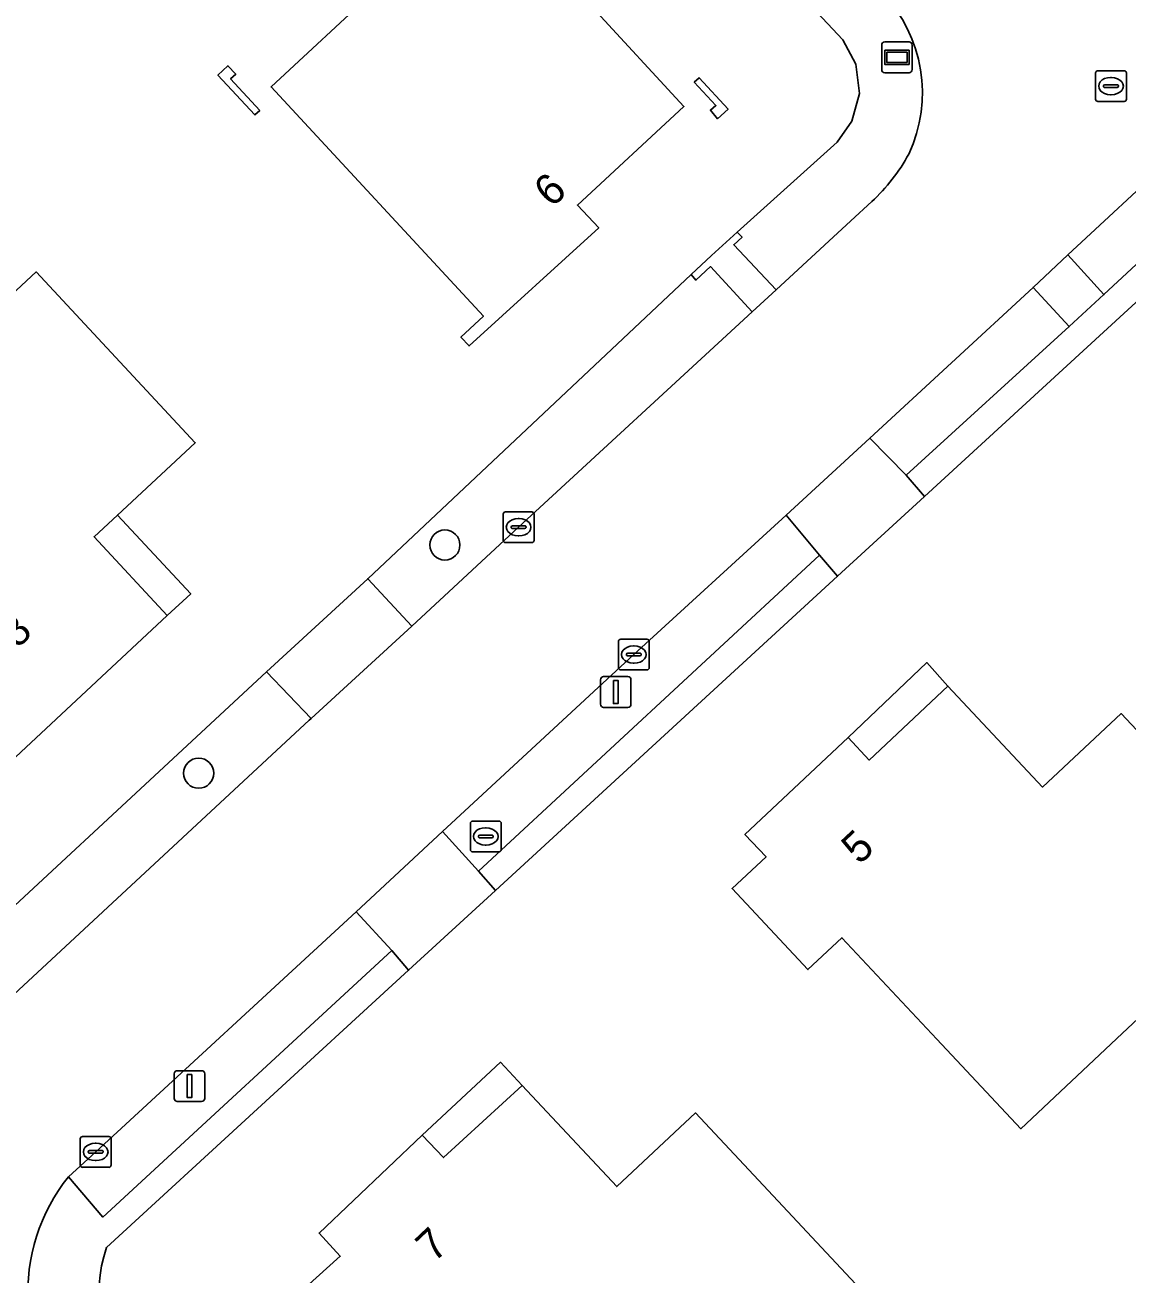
# Model space of a CAD drawing. Extents: x 162661 to 163484, y 380247 to 381230.
# Drawn here: x 163294.19 to 163329.99, y 380893.22 to 380933.79 of the extents above; entities that cross this region are included whole.
import ezdxf

# ---------------------------------------------------------------- set-up
doc = ezdxf.new("R2010")
doc.units = 0
for name, color, linetype in [('IMGEO_Berm_groen', 7, 'Continuous'), ('IMGEO_Boom', 7, 'Continuous'), ('IMGEO_Brandkraan', 7, 'Continuous'), ('IMGEO_Erf', 7, 'Continuous'), ('IMGEO_Groenvoorziening', 7, 'Continuous'), ('IMGEO_Haag', 7, 'Continuous'), ('IMGEO_Kolk', 7, 'Continuous'), ('IMGEO_Lichtmast', 7, 'Continuous'), ('IMGEO_Pand', 7, 'Continuous'), ('IMGEO_Pand_nummerreeks', 7, 'Continuous'), ('IMGEO_Pand_overbouw', 7, 'Continuous'), ('IMGEO_Parkeervlak_halfverhard', 7, 'Continuous'), ('IMGEO_Rijbaan_lokaal_gesloten', 7, 'Continuous'), ('IMGEO_Rioolput', 7, 'Continuous'), ('IMGEO_Straatnaambord', 7, 'Continuous'), ('IMGEO_Voetpad_open', 7, 'Continuous')]:
    doc.layers.add(name, color=color, linetype=linetype)

msp = doc.modelspace()

# ---------------------------------------------------------------- linework, layer by layer
at = {"layer": 'IMGEO_Berm_groen'}
for points in [[(163293.024, 380958.913), (163294.252, 380959.688), (163295.699, 380959.641), (163296.884, 380958.739), (163320.761, 380933.306), (163321.184, 380932.515), (163321.299, 380931.564), (163321.057, 380930.657), (163320.579, 380929.984), (163317.332, 380927.055), (163317.486, 380926.898), (163317.218, 380926.646), (163318.596, 380925.187), (163321.019, 380927.42), (163321.7, 380928.048)], [(163296.844, 380894.082), (163306.653, 380903.087), (163306.114, 380903.726), (163296.724, 380895.071), (163295.607, 380896.382)]]:
    msp.add_lwpolyline(points, dxfattribs=at)
for points in [[(163317.82, 380924.471), (163316.465, 380925.941), (163315.99, 380925.496), (163315.837, 380925.681), (163305.328, 380915.802), (163306.754, 380914.26), (163310.229, 380917.474)], [(163292.603, 380901.179), (163303.421, 380911.205), (163303.486, 380911.264), (163302.041, 380912.777), (163278.098, 380890.562), (163279.38, 380889.205), (163283.878, 380893.181), (163284.042, 380893.331)]]:
    msp.add_lwpolyline(points, close=True, dxfattribs=at)
for centre, radius, start, end in [((163318.634, 380931.58), 4.71, 335.074, 43.3446), ((163317.482, 380932.576), 6.188, 312.9676, 331.2004), ((163300.314, 380892.617), 6.028, 141.3438, 183.419), ((163300.705, 380892.693), 4.103, 160.2199, 228.0468)]:
    msp.add_arc(centre, radius, start, end, dxfattribs=at)
at = {"layer": 'IMGEO_Boom'}
for centre in [(163307.833, 380916.898), (163299.834, 380909.487)]:
    msp.add_circle(centre, 0.489, dxfattribs=at)
at = {"layer": 'IMGEO_Brandkraan'}
for p, q in [((163308.661, 380907.006), (163308.661, 380907.858)), ((163308.736, 380907.932), (163309.588, 380907.932)), ((163309.149, 380907.712), (163309.174, 380907.712)), ((163309.662, 380907.858), (163309.662, 380907.006)), ((163308.92, 380907.426), (163308.92, 380907.438)), ((163309.358, 380907.389), (163308.96, 380907.389)), ((163308.963, 380907.475), (163309.361, 380907.475)), ((163309.404, 380907.438), (163309.404, 380907.426)), ((163309.588, 380906.932), (163308.736, 380906.932)), ((163309.172, 380907.152), (163309.147, 380907.152))]:
    msp.add_line(p, q, dxfattribs=at)
for points in [[(163308.661, 380907.006), (163308.661, 380907.858)], [(163308.736, 380907.932), (163309.588, 380907.932)], [(163309.662, 380907.858), (163309.662, 380907.006)], [(163309.588, 380906.932), (163308.736, 380906.932)]]:
    msp.add_lwpolyline(points, dxfattribs=at)
for centre, radius, start, end in [((163308.738, 380907.856), 0.0765, 91.552, 178.448), ((163308.738, 380907.856), 0.0765, 91.552, 178.448), ((163309.586, 380907.856), 0.0765, 1.552, 88.448), ((163309.586, 380907.856), 0.0765, 1.552, 88.448), ((163308.96, 380907.435), 0.0403, 85.8775, 175.7526), ((163308.957, 380907.425), 0.0366, 178.938, 274.7102), ((163309.361, 380907.432), 0.043, 264.8664, 352.4533), ((163309.365, 380907.437), 0.0386, 1.7309, 96.639), ((163308.738, 380907.008), 0.0765, 181.552, 268.448), ((163308.738, 380907.008), 0.0765, 181.552, 268.448), ((163309.586, 380907.008), 0.0765, 271.552, 358.448), ((163309.586, 380907.008), 0.0765, 271.552, 358.448)]:
    msp.add_arc(centre, radius, start, end, dxfattribs=at)
for centre, major_axis, ratio, start_param, end_param in [((163309.148, 380907.432), (-0.387, 0.002), 0.722429, 4.712389, 7.853982), ((163309.173, 380907.432), (-0.39, 0.002), 0.717154, 1.570796, 4.712389)]:
    msp.add_ellipse(centre, major_axis=major_axis, ratio=ratio, start_param=start_param, end_param=end_param, dxfattribs=at)
at = {"layer": 'IMGEO_Erf'}
for points in [[(163404.993, 380933.536), (163403.462, 380935.161), (163390.657, 380948.856), (163386.451, 380953.455), (163376.71, 380963.784), (163373.198, 380964.214), (163372.923, 380964.017), (163339.792, 380933.51), (163323.416, 380918.477), (163320.591, 380915.883), (163309.478, 380905.68), (163306.653, 380903.087), (163296.844, 380894.082)], [(163278.098, 380890.562), (163302.041, 380912.777), (163305.328, 380915.802), (163315.837, 380925.681), (163316.494, 380926.299), (163317.332, 380927.055), (163320.579, 380929.984), (163321.057, 380930.657), (163321.299, 380931.564), (163321.184, 380932.515), (163320.761, 380933.306), (163296.884, 380958.739), (163295.699, 380959.641), (163294.252, 380959.688), (163293.024, 380958.913), (163283.361, 380949.868), (163280.252, 380946.958), (163279.693, 380946.435), (163279.155, 380946.024), (163267.646, 380936.418), (163264.752, 380934.006)]]:
    msp.add_lwpolyline(points, dxfattribs=at)
for points in [[(163302.185, 380931.776), (163305.624, 380934.965), (163304.635, 380936.032), (163308.825, 380939.918), (163309.065, 380939.658), (163308.326, 380938.983), (163309.719, 380937.481), (163310.453, 380938.16), (163313.364, 380935.016), (163312.639, 380934.34), (163315.599, 380931.142), (163312.137, 380927.939), (163312.833, 380927.195), (163308.617, 380923.363), (163308.352, 380923.649), (163309.083, 380924.327)], [(163300.46, 380932.16), (163300.786, 380932.463), (163301.041, 380932.188), (163300.872, 380932.032), (163301.821, 380931.009), (163301.663, 380930.863)], [(163315.932, 380931.927), (163316.09, 380932.073), (163317.034, 380931.053), (163316.692, 380930.741), (163316.459, 380931.022), (163316.635, 380931.168)], [(163289.384, 380920.952), (163294.56, 380925.767), (163299.721, 380920.22), (163297.196, 380917.871), (163296.437, 380917.165), (163298.814, 380914.61), (163292.897, 380909.095), (163292.215, 380909.827), (163291.121, 380908.79), (163288.672, 380911.424), (163289.774, 380912.45), (163287.391, 380915.013), (163291.421, 380918.761)], [(163329.836, 380901.028), (163326.546, 380897.941), (163323.815, 380900.853), (163320.728, 380904.144), (163319.628, 380903.111), (163317.164, 380905.738), (163318.266, 380906.772), (163317.581, 380907.499), (163320.931, 380910.641), (163321.617, 380909.914), (163324.172, 380912.316), (163327.25, 380909.035), (163329.806, 380911.425), (163335.008, 380905.88)], [(163313.418, 380896.062), (163315.974, 380898.453), (163321.176, 380892.908), (163316.004, 380888.056), (163313.273, 380890.967), (163310.003, 380887.9), (163306.825, 380891.161), (163305.766, 380890.171), (163303.313, 380892.798), (163304.434, 380893.8), (163303.747, 380894.55), (163307.099, 380897.73), (163307.787, 380897.005), (163310.338, 380899.346)]]:
    msp.add_lwpolyline(points, close=True, dxfattribs=at)
msp.add_arc((163300.705, 380892.693), 4.103, 160.2199, 228.0468, dxfattribs=at)
at = {"layer": 'IMGEO_Groenvoorziening'}
msp.add_lwpolyline([(163378.593, 380962.733), (163378.306, 380963.06), (163378.763, 380963.459), (163374.975, 380967.47), (163374.087, 380966.646), (163329.24, 380925.031), (163328.116, 380923.988), (163322.814, 380919.162), (163323.416, 380918.477), (163339.792, 380933.51), (163372.923, 380964.017), (163373.198, 380964.214), (163376.71, 380963.784), (163386.451, 380953.455), (163390.657, 380948.856), (163403.462, 380935.161), (163404.993, 380933.536)], dxfattribs=at)
msp.add_lwpolyline([(163320.591, 380915.883), (163320.001, 380916.57), (163308.921, 380906.309), (163309.478, 380905.68)], close=True, dxfattribs=at)
at = {"layer": 'IMGEO_Haag'}
msp.add_lwpolyline([(163320.591, 380915.883), (163320.001, 380916.57), (163308.921, 380906.309), (163309.478, 380905.68)], close=True, dxfattribs=at)
at = {"layer": 'IMGEO_Kolk'}
for p, q in [((163309.728, 380917.048), (163309.728, 380917.9)), ((163309.803, 380917.974), (163310.655, 380917.974)), ((163310.729, 380917.9), (163310.729, 380917.048)), ((163309.987, 380917.468), (163309.987, 380917.48)), ((163310.425, 380917.431), (163310.027, 380917.431)), ((163310.03, 380917.517), (163310.428, 380917.517)), ((163310.216, 380917.754), (163310.241, 380917.754)), ((163310.471, 380917.48), (163310.471, 380917.468)), ((163310.655, 380916.974), (163309.803, 380916.974)), ((163310.239, 380917.194), (163310.214, 380917.194)), ((163313.469, 380912.913), (163313.469, 380913.765)), ((163313.544, 380913.839), (163314.396, 380913.839)), ((163314.47, 380913.765), (163314.47, 380912.913)), ((163313.728, 380913.333), (163313.728, 380913.345)), ((163313.771, 380913.382), (163314.169, 380913.382)), ((163313.957, 380913.619), (163313.982, 380913.619)), ((163314.212, 380913.345), (163314.212, 380913.333)), ((163314.166, 380913.296), (163313.768, 380913.296)), ((163313.98, 380913.059), (163313.955, 380913.059)), ((163314.396, 380912.839), (163313.544, 380912.839)), ((163295.989, 380896.761), (163295.989, 380897.613)), ((163296.064, 380897.687), (163296.916, 380897.687)), ((163296.99, 380897.613), (163296.99, 380896.761)), ((163296.248, 380897.181), (163296.248, 380897.193)), ((163296.686, 380897.144), (163296.288, 380897.144)), ((163296.291, 380897.23), (163296.689, 380897.23)), ((163296.477, 380897.467), (163296.502, 380897.467)), ((163296.732, 380897.193), (163296.732, 380897.181)), ((163296.916, 380896.687), (163296.064, 380896.687)), ((163296.5, 380896.907), (163296.475, 380896.907))]:
    msp.add_line(p, q, dxfattribs=at)
for points in [[(163309.728, 380917.048), (163309.728, 380917.9)], [(163309.803, 380917.974), (163310.655, 380917.974)], [(163310.729, 380917.9), (163310.729, 380917.048)], [(163310.655, 380916.974), (163309.803, 380916.974)], [(163313.469, 380912.913), (163313.469, 380913.765)], [(163313.544, 380913.839), (163314.396, 380913.839)], [(163314.47, 380913.765), (163314.47, 380912.913)], [(163314.396, 380912.839), (163313.544, 380912.839)], [(163295.989, 380896.761), (163295.989, 380897.613)], [(163296.064, 380897.687), (163296.916, 380897.687)], [(163296.99, 380897.613), (163296.99, 380896.761)], [(163296.916, 380896.687), (163296.064, 380896.687)]]:
    msp.add_lwpolyline(points, dxfattribs=at)
for centre, radius, start, end in [((163309.805, 380917.898), 0.0765, 91.552, 178.448), ((163309.805, 380917.898), 0.0765, 91.552, 178.448), ((163310.653, 380917.898), 0.0765, 1.552, 88.448), ((163310.653, 380917.898), 0.0765, 1.552, 88.448), ((163310.027, 380917.477), 0.0403, 85.8775, 175.7526), ((163310.024, 380917.467), 0.0366, 178.938, 274.7102), ((163310.428, 380917.474), 0.043, 264.8664, 352.4533), ((163310.432, 380917.479), 0.0386, 1.7309, 96.639), ((163309.805, 380917.05), 0.0765, 181.552, 268.448), ((163309.805, 380917.05), 0.0765, 181.552, 268.448), ((163310.653, 380917.05), 0.0765, 271.552, 358.448), ((163310.653, 380917.05), 0.0765, 271.552, 358.448), ((163313.546, 380913.763), 0.0765, 91.552, 178.448), ((163313.546, 380913.763), 0.0765, 91.552, 178.448), ((163314.394, 380913.763), 0.0765, 1.552, 88.448), ((163314.394, 380913.763), 0.0765, 1.552, 88.448), ((163313.768, 380913.342), 0.0403, 85.8775, 175.7526), ((163313.765, 380913.332), 0.0366, 178.938, 274.7102), ((163314.169, 380913.339), 0.043, 264.8664, 352.4533), ((163314.173, 380913.344), 0.0386, 1.7309, 96.639), ((163313.546, 380912.915), 0.0765, 181.552, 268.448), ((163313.546, 380912.915), 0.0765, 181.552, 268.448), ((163314.394, 380912.915), 0.0765, 271.552, 358.448), ((163314.394, 380912.915), 0.0765, 271.552, 358.448), ((163296.066, 380897.611), 0.0765, 91.552, 178.448), ((163296.066, 380897.611), 0.0765, 91.552, 178.448), ((163296.914, 380897.611), 0.0765, 1.552, 88.448), ((163296.914, 380897.611), 0.0765, 1.552, 88.448), ((163296.288, 380897.19), 0.0403, 85.8775, 175.7526), ((163296.285, 380897.18), 0.0366, 178.938, 274.7102), ((163296.689, 380897.187), 0.043, 264.8664, 352.4533), ((163296.693, 380897.192), 0.0386, 1.7309, 96.639), ((163296.066, 380896.763), 0.0765, 181.552, 268.448), ((163296.066, 380896.763), 0.0765, 181.552, 268.448), ((163296.914, 380896.763), 0.0765, 271.552, 358.448), ((163296.914, 380896.763), 0.0765, 271.552, 358.448)]:
    msp.add_arc(centre, radius, start, end, dxfattribs=at)
for centre, major_axis, ratio, start_param, end_param in [((163310.215, 380917.474), (-0.387, 0.002), 0.722429, 4.712389, 7.853982), ((163310.24, 380917.474), (-0.39, 0.002), 0.717154, 1.570796, 4.712389), ((163313.956, 380913.339), (-0.387, 0.002), 0.722429, 4.712389, 7.853982), ((163313.981, 380913.339), (-0.39, 0.002), 0.717154, 1.570796, 4.712389), ((163296.476, 380897.187), (-0.387, 0.002), 0.722429, 4.712389, 7.853982), ((163296.501, 380897.187), (-0.39, 0.002), 0.717154, 1.570796, 4.712389)]:
    msp.add_ellipse(centre, major_axis=major_axis, ratio=ratio, start_param=start_param, end_param=end_param, dxfattribs=at)
at = {"layer": 'IMGEO_Lichtmast'}
for p, q in [((163312.888, 380911.724), (163312.888, 380912.524)), ((163312.888, 380912.524), (163312.888, 380911.724)), ((163312.988, 380912.624), (163313.778, 380912.624)), ((163313.778, 380912.624), (163312.988, 380912.624)), ((163313.878, 380912.524), (163313.878, 380911.724)), ((163313.878, 380911.724), (163313.878, 380912.524)), ((163313.778, 380911.624), (163312.988, 380911.624)), ((163312.988, 380911.624), (163313.778, 380911.624)), ((163299.041, 380898.925), (163299.041, 380899.725)), ((163299.041, 380899.725), (163299.041, 380898.925)), ((163299.141, 380899.825), (163299.931, 380899.825)), ((163299.931, 380899.825), (163299.141, 380899.825)), ((163300.031, 380899.725), (163300.031, 380898.925)), ((163300.031, 380898.925), (163300.031, 380899.725)), ((163299.931, 380898.825), (163299.141, 380898.825)), ((163299.141, 380898.825), (163299.931, 380898.825))]:
    msp.add_line(p, q, dxfattribs=at)
for points in [[(163313.308, 380912.499), (163313.458, 380912.499), (163313.458, 380911.749), (163313.308, 380911.749), (163313.308, 380912.499)], [(163299.461, 380899.7), (163299.611, 380899.7), (163299.611, 380898.95), (163299.461, 380898.95), (163299.461, 380899.7)]]:
    msp.add_lwpolyline(points, dxfattribs=at)
for centre, start, end in [((163312.988, 380912.524), 90, 180), ((163312.988, 380912.524), 90, 180), ((163313.778, 380912.524), 0, 90), ((163313.778, 380912.524), 360, 90), ((163312.988, 380911.724), 180, 270), ((163312.988, 380911.724), 180, 270), ((163313.778, 380911.724), 270, 0), ((163313.778, 380911.724), 270, 0), ((163299.141, 380899.725), 90, 180), ((163299.141, 380899.725), 90, 180), ((163299.931, 380899.725), 0, 90), ((163299.931, 380899.725), 360, 90), ((163299.141, 380898.925), 180, 270), ((163299.141, 380898.925), 180, 270), ((163299.931, 380898.925), 270, 0), ((163299.931, 380898.925), 270, 0)]:
    msp.add_arc(centre, 0.1, start, end, dxfattribs=at)
at = {"layer": 'IMGEO_Pand'}
for points in [[(163312.639, 380934.34), (163313.364, 380935.016), (163310.453, 380938.16), (163309.719, 380937.481), (163308.326, 380938.983), (163309.065, 380939.658), (163308.825, 380939.918), (163304.635, 380936.032), (163305.624, 380934.965), (163302.185, 380931.776), (163309.083, 380924.327), (163308.352, 380923.649), (163308.617, 380923.363), (163312.833, 380927.195), (163312.137, 380927.939), (163315.599, 380931.142)], [(163300.786, 380932.463), (163300.46, 380932.16), (163301.663, 380930.863), (163301.821, 380931.009), (163300.872, 380932.032), (163301.041, 380932.188)], [(163316.09, 380932.073), (163315.932, 380931.927), (163316.635, 380931.168), (163316.459, 380931.022), (163316.692, 380930.741), (163317.034, 380931.053)], [(163298.814, 380914.61), (163296.437, 380917.165), (163297.196, 380917.871), (163299.721, 380920.22), (163294.56, 380925.767), (163289.384, 380920.952), (163291.421, 380918.761), (163287.391, 380915.013), (163289.774, 380912.45), (163288.672, 380911.424), (163291.121, 380908.79), (163292.215, 380909.827), (163292.897, 380909.095)], [(163329.806, 380911.425), (163327.25, 380909.035), (163324.172, 380912.316), (163321.617, 380909.914), (163320.931, 380910.641), (163317.581, 380907.499), (163318.266, 380906.772), (163317.164, 380905.738), (163319.628, 380903.111), (163320.728, 380904.144), (163323.815, 380900.853), (163326.546, 380897.941), (163329.836, 380901.028), (163335.008, 380905.88)], [(163307.099, 380897.73), (163303.747, 380894.55), (163304.434, 380893.8), (163303.313, 380892.798), (163305.766, 380890.171), (163306.825, 380891.161), (163310.003, 380887.9), (163313.273, 380890.967), (163316.004, 380888.056), (163321.176, 380892.908), (163315.974, 380898.453), (163313.418, 380896.062), (163310.338, 380899.346), (163307.787, 380897.005)]]:
    msp.add_lwpolyline(points, close=True, dxfattribs=at)
at = {"layer": 'IMGEO_Pand_overbouw'}
for points in [[(163298.814, 380914.61), (163299.575, 380915.314), (163297.196, 380917.871), (163296.437, 380917.165)], [(163324.172, 380912.316), (163323.487, 380913.079), (163320.931, 380910.641), (163321.617, 380909.914)], [(163310.338, 380899.346), (163309.636, 380900.099), (163307.099, 380897.73), (163307.787, 380897.005)]]:
    msp.add_lwpolyline(points, close=True, dxfattribs=at)
at = {"layer": 'IMGEO_Parkeervlak_halfverhard'}
for points in [[(163374.087, 380966.646), (163374.975, 380967.47), (163373.827, 380968.685), (163373.428, 380968.316), (163373.301, 380968.198), (163365.821, 380961.281), (163348.662, 380945.375), (163331.476, 380929.483), (163328.071, 380926.319), (163329.24, 380925.031)], [(163328.116, 380923.988), (163326.94, 380925.261), (163321.632, 380920.366), (163322.814, 380919.162)], [(163320.001, 380916.57), (163318.915, 380917.861), (163313.97, 380913.339), (163307.754, 380907.59), (163308.921, 380906.309)], [(163306.114, 380903.726), (163304.951, 380904.985), (163296.49, 380897.187), (163295.607, 380896.382), (163296.724, 380895.071)]]:
    msp.add_lwpolyline(points, close=True, dxfattribs=at)
at = {"layer": 'IMGEO_Rijbaan_lokaal_gesloten'}
for points in [[(163318.915, 380917.861), (163321.632, 380920.366), (163326.94, 380925.261), (163328.071, 380926.319), (163331.476, 380929.483), (163348.662, 380945.375), (163365.821, 380961.281), (163373.301, 380968.198), (163373.428, 380968.316), (163369.571, 380972.49), (163369.035, 380971.991), (163355.608, 380959.493), (163352.811, 380956.889), (163346.451, 380950.969), (163343.629, 380948.342), (163333.656, 380939.059)], [(163321.7, 380928.048), (163321.019, 380927.42), (163318.596, 380925.187), (163317.82, 380924.471), (163310.229, 380917.474), (163306.754, 380914.26), (163303.486, 380911.264), (163303.421, 380911.205), (163292.603, 380901.179), (163284.042, 380893.331), (163283.878, 380893.181), (163279.38, 380889.205), (163276.68, 380886.933)], [(163295.607, 380896.382), (163296.49, 380897.187), (163304.951, 380904.985), (163307.754, 380907.59), (163313.97, 380913.339), (163318.915, 380917.861)]]:
    msp.add_lwpolyline(points, dxfattribs=at)
for centre, radius, start, end in [((163318.634, 380931.58), 4.71, 335.074, 43.3446), ((163317.482, 380932.576), 6.188, 312.9676, 331.2004), ((163300.314, 380892.617), 6.028, 141.3438, 183.419)]:
    msp.add_arc(centre, radius, start, end, dxfattribs=at)
at = {"layer": 'IMGEO_Rioolput'}
for p, q in [((163328.971, 380931.374), (163328.971, 380932.226)), ((163329.046, 380932.3), (163329.898, 380932.3)), ((163329.459, 380932.08), (163329.484, 380932.08)), ((163329.972, 380932.226), (163329.972, 380931.374)), ((163329.23, 380931.794), (163329.23, 380931.806)), ((163329.668, 380931.757), (163329.27, 380931.757)), ((163329.273, 380931.843), (163329.671, 380931.843)), ((163329.714, 380931.806), (163329.714, 380931.794)), ((163329.898, 380931.3), (163329.046, 380931.3)), ((163329.482, 380931.52), (163329.457, 380931.52))]:
    msp.add_line(p, q, dxfattribs=at)
for points in [[(163328.971, 380931.374), (163328.971, 380932.226)], [(163329.046, 380932.3), (163329.898, 380932.3)], [(163329.972, 380932.226), (163329.972, 380931.374)], [(163329.898, 380931.3), (163329.046, 380931.3)]]:
    msp.add_lwpolyline(points, dxfattribs=at)
for centre, radius, start, end in [((163329.048, 380932.224), 0.0765, 91.552, 178.448), ((163329.048, 380932.224), 0.0765, 91.552, 178.448), ((163329.896, 380932.224), 0.0765, 1.552, 88.448), ((163329.896, 380932.224), 0.0765, 1.552, 88.448), ((163329.27, 380931.803), 0.0403, 85.8775, 175.7526), ((163329.267, 380931.793), 0.0366, 178.938, 274.7102), ((163329.671, 380931.8), 0.043, 264.8664, 352.4533), ((163329.675, 380931.805), 0.0386, 1.7309, 96.639), ((163329.048, 380931.376), 0.0765, 181.552, 268.448), ((163329.048, 380931.376), 0.0765, 181.552, 268.448), ((163329.896, 380931.376), 0.0765, 271.552, 358.448), ((163329.896, 380931.376), 0.0765, 271.552, 358.448)]:
    msp.add_arc(centre, radius, start, end, dxfattribs=at)
for centre, major_axis, ratio, start_param, end_param in [((163329.458, 380931.8), (-0.387, 0.002), 0.722429, 4.712389, 7.853982), ((163329.483, 380931.8), (-0.39, 0.002), 0.717154, 1.570796, 4.712389)]:
    msp.add_ellipse(centre, major_axis=major_axis, ratio=ratio, start_param=start_param, end_param=end_param, dxfattribs=at)
at = {"layer": 'IMGEO_Straatnaambord'}
for p, q in [((163322.123, 380933.235), (163322.913, 380933.235)), ((163322.913, 380933.235), (163322.123, 380933.235)), ((163322.023, 380932.335), (163322.023, 380933.135)), ((163322.023, 380933.135), (163322.023, 380932.335)), ((163323.013, 380933.135), (163323.013, 380932.335)), ((163323.013, 380932.335), (163323.013, 380933.135)), ((163322.913, 380932.235), (163322.123, 380932.235)), ((163322.123, 380932.235), (163322.913, 380932.235))]:
    msp.add_line(p, q, dxfattribs=at)
for points in [[(163322.124, 380932.967), (163322.912, 380932.967), (163322.912, 380932.503), (163322.124, 380932.503), (163322.124, 380932.967)], [(163322.189, 380932.902), (163322.189, 380932.568), (163322.847, 380932.568), (163322.847, 380932.902), (163322.189, 380932.902)]]:
    msp.add_lwpolyline(points, dxfattribs=at)
for centre, start, end in [((163322.123, 380933.135), 90, 180), ((163322.123, 380933.135), 90, 180), ((163322.913, 380933.135), 0, 90), ((163322.913, 380933.135), 360, 90), ((163322.123, 380932.335), 180, 270), ((163322.123, 380932.335), 180, 270), ((163322.913, 380932.335), 270, 0), ((163322.913, 380932.335), 270, 0)]:
    msp.add_arc(centre, 0.1, start, end, dxfattribs=at)
at = {"layer": 'IMGEO_Voetpad_open'}
for points in [[(163317.218, 380926.646), (163317.486, 380926.898), (163317.332, 380927.055), (163316.494, 380926.299), (163315.837, 380925.681), (163315.99, 380925.496), (163316.465, 380925.941), (163317.82, 380924.471), (163318.596, 380925.187)], [(163326.94, 380925.261), (163328.116, 380923.988), (163329.24, 380925.031), (163328.071, 380926.319)], [(163318.915, 380917.861), (163320.001, 380916.57), (163320.591, 380915.883), (163323.416, 380918.477), (163322.814, 380919.162), (163321.632, 380920.366)], [(163306.754, 380914.26), (163305.328, 380915.802), (163302.041, 380912.777), (163303.486, 380911.264)], [(163309.478, 380905.68), (163308.921, 380906.309), (163307.754, 380907.59), (163304.951, 380904.985), (163306.114, 380903.726), (163306.653, 380903.087)]]:
    msp.add_lwpolyline(points, close=True, dxfattribs=at)

# ---------------------------------------------------------------- texts
at = {"layer": 'IMGEO_Pand_nummerreeks'}
for s, rotation, p in [('6', 42.2671, (163311.298, 380927.827)), ('8', 42.9809, (163293.94, 380913.511)), ('5', 43.1666, (163321.299, 380906.489)), ('7', 43.494, (163307.481, 380893.571))]:
    msp.add_text(s, height=1, rotation=rotation, dxfattribs=at).set_placement(p)

doc.saveas('drawing.dxf')
